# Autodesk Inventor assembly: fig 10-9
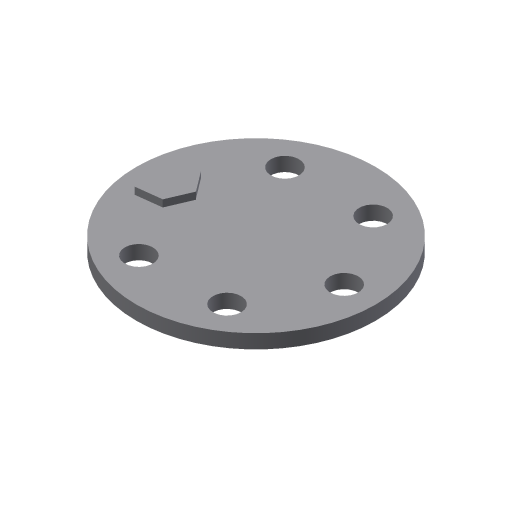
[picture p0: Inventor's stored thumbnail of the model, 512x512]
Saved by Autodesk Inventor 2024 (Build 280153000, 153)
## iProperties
Created: 2008-05
Part Number: fig 10-9
Document SubType Name: Assembly
Designer: CADCIM
Author: CADCIM
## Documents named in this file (3)
- D:\PROJECTS\Project 2023\RESOURCES INVENTOR 2024\RESOURCES INVENTOR 2024\Inventor_2023_Part\Inventor_2024_Part\c10_Inv_2024_prt\fig 10-9.iam
- D:\PROJECTS\Project 2023\RESOURCES INVENTOR 2024\RESOURCES INVENTOR 2024\Inventor_2023_Part\Inventor_2024_Part\c10_Inv_2024_prt\Part4.ipt
- D:\PROJECTS\Project 2023\RESOURCES INVENTOR 2024\RESOURCES INVENTOR 2024\Inventor_2023_Part\Inventor_2024_Part\c10_Inv_2024_prt\Part5.ipt
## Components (2 placed, 2 different names)
1. Part4:1
2. Part5:1
